// Mitsubishi GX Works2 project: MC-24MR-4MT-430-FX-B)例程   PLC: FX1S

PROGRAM MAIN
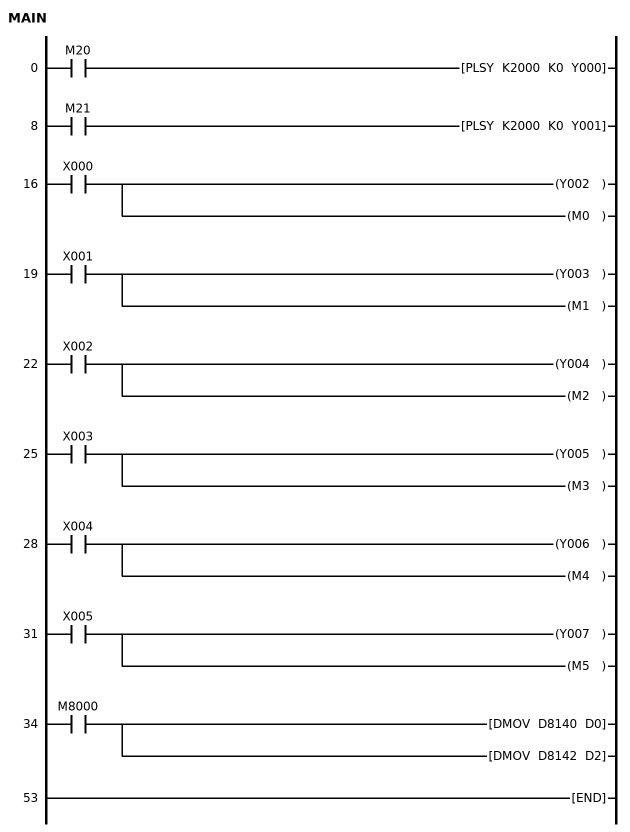
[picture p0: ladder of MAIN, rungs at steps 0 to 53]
0     LD      M20
      PLSY    K2000 K0 Y000
8     LD      M21
      PLSY    K2000 K0 Y001
16    LD      X000
      OUT     Y002
      OUT     M0
19    LD      X001
      OUT     Y003
      OUT     M1
22    LD      X002
      OUT     Y004
      OUT     M2
25    LD      X003
      OUT     Y005
      OUT     M3
28    LD      X004
      OUT     Y006
      OUT     M4
31    LD      X005
      OUT     Y007
      OUT     M5
34    LD      M8000
      DMOV    D8140 D0
      DMOV    D8142 D2
53    END
END_PROGRAM
